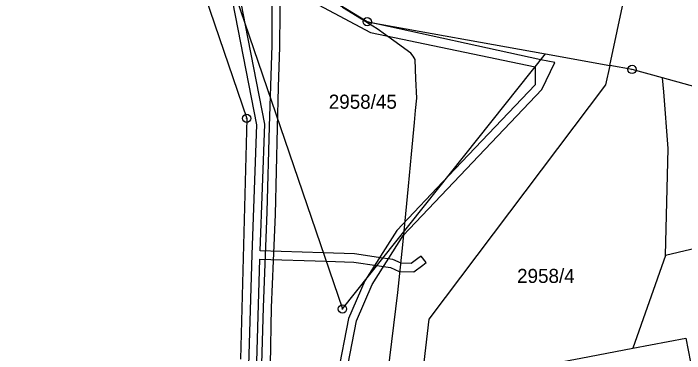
# Model space of a CAD drawing. Extents: x -621168 to -620292, y -1122748 to -1122069.
# Drawn here: x -620574.7 to -620493.7, y -1122640.4 to -1122599.3 of the extents above; entities that cross this region are included whole.
import ezdxf

# ---------------------------------------------------------------- set-up
doc = ezdxf.new("R2010")
doc.units = 0
for name, color, linetype in [('GasNet', 7, 'Continuous'), ('Hranice parcel', 7, 'Continuous'), ('Parcelní čísla', 7, 'Continuous'), ('VAS stoka', 7, 'Continuous'), ('VAS vodovod', 7, 'Continuous'), ('Vnitřní kresba', 7, 'Continuous'), ('Věcná břemena k části', 7, 'Continuous'), ('Značky bodu BP', 7, 'Continuous')]:
    doc.layers.add(name, color=color, linetype=linetype)

msp = doc.modelspace()

# ---------------------------------------------------------------- linework, layer by layer
at = {"layer": 'GasNet'}
msp.add_lwpolyline([(-620543.45, -1122595.16), (-620543.47, -1122603.15), (-620543.79, -1122613), (-620544.07, -1122623.3), (-620544.52, -1122634.84), (-620544.92, -1122648.49), (-620545.38, -1122658.87), (-620545.7, -1122668.76), (-620545.98, -1122679.66), (-620545.725, -1122687.651)], dxfattribs=at)
at = {"layer": 'Hranice parcel'}
for p, q in [((-620510.44, -1122604.21), (-620502.69, -1122605.61)), ((-620546.5, -1122612), (-620547.23, -1122641.1))]:
    msp.add_line(p, q, dxfattribs=at)
for points in [[(-620581.67, -1122552.32), (-620562.67, -1122564.59), (-620546.5, -1122612)], [(-620562.8, -1122553.35), (-620548.28, -1122570.88), (-620537.83, -1122596.73), (-620531.96, -1122600.32), (-620510.44, -1122604.21)], [(-620562.8, -1122553.35), (-620534.95, -1122635.03), (-620510.44, -1122604.21)], [(-620502.69, -1122605.61), (-620500.92, -1122597.26), (-620501.2, -1122595.75)], [(-620502.69, -1122605.61), (-620503.19, -1122607.95), (-620524.52, -1122636.25), (-620525.13, -1122641.47), (-620525.33, -1122649.53), (-620522.29, -1122666.99)], [(-620496.31, -1122607.11), (-620500, -1122606.09), (-620502.69, -1122605.61)], [(-620485.31, -1122626.04), (-620487.46, -1122626.56), (-620495.96, -1122628.58), (-620495.65, -1122615.65), (-620496.18, -1122608.79), (-620496.31, -1122607.11)], [(-620478.83, -1122611.96), (-620480.79, -1122611.41), (-620496.31, -1122607.11)], [(-620522.29, -1122666.99), (-620515.05, -1122665.61), (-620511.55, -1122664.94), (-620512.68, -1122659.03), (-620515.78, -1122642.8), (-620506.17, -1122640.97), (-620499.9, -1122639.77), (-620493.5, -1122638.55), (-620492.94, -1122641.47), (-620486.3, -1122676.15)]]:
    msp.add_lwpolyline(points, dxfattribs=at)
at = {"layer": 'VAS stoka'}
msp.add_lwpolyline([(-620529.696, -1122644.88), (-620528.987, -1122638.954), (-620528.278, -1122633.029), (-620527.953, -1122629.96), (-620527.627, -1122626.89), (-620527.309, -1122623.538), (-620526.991, -1122620.187), (-620526.62, -1122616.34), (-620526.248, -1122612.494), (-620526.118, -1122611.034), (-620525.987, -1122609.574), (-620526.074, -1122607.233), (-620526.16, -1122604.893), (-620526.431, -1122604.504), (-620526.702, -1122604.116), (-620528.728, -1122602.652), (-620530.754, -1122601.188), (-620532.839, -1122599.89), (-620534.923, -1122598.593)], dxfattribs=at)
at = {"layer": 'VAS vodovod'}
msp.add_lwpolyline([(-620544.967, -1122587.097), (-620544.948, -1122587.248), (-620544.929, -1122587.398), (-620544.87, -1122587.521), (-620544.812, -1122587.644), (-620544.235, -1122589.495), (-620543.658, -1122591.345), (-620543.047, -1122593.188), (-620542.435, -1122595.031), (-620542.492, -1122599.187), (-620542.549, -1122603.343), (-620542.689, -1122608.247), (-620542.829, -1122613.151), (-620542.948, -1122618.376), (-620543.067, -1122623.6), (-620543.31, -1122629.222), (-620543.553, -1122634.844), (-620543.681, -1122641.775)], dxfattribs=at)
at = {"layer": 'Vnitřní kresba'}
msp.add_line((-620495.96, -1122628.58), (-620499.9, -1122639.77), dxfattribs=at)
at = {"layer": 'Věcná břemena k části'}
for points in [[(-620534.53, -1122643.11), (-620533.24, -1122636.48), (-620531.35, -1122632.09), (-620527.61, -1122626.14), (-620510.87, -1122608.51), (-620509.33, -1122605.27), (-620511, -1122604.91), (-620531.96, -1122600.32), (-620537.83, -1122596.73), (-620543.57, -1122594.05), (-620549.38, -1122589.64), (-620555.33, -1122573.96), (-620556.49, -1122571.86), (-620550.21, -1122590.27), (-620544.11, -1122594.89), (-620531.56, -1122601.62), (-620511.69, -1122605.79), (-620511.71, -1122607.93), (-620522.17, -1122618.96), (-620528.4, -1122625.53), (-620532.24, -1122631.63), (-620534.2, -1122636.18), (-620535.53, -1122643.03)], [(-620545.91, -1122663.42), (-620544.9, -1122629), (-620536.91, -1122629.27), (-620533.56, -1122629.38), (-620530.78, -1122629.78), (-620529.16, -1122630.02), (-620528.1, -1122630.5), (-620526.34, -1122630.56), (-620525.24, -1122629.73), (-620524.84, -1122629.43), (-620525.44, -1122628.63), (-620525.84, -1122628.93), (-620526.66, -1122629.54), (-620527.88, -1122629.5), (-620528.88, -1122629.06), (-620530.06, -1122628.89), (-620533.48, -1122628.38), (-620537.26, -1122628.25), (-620544.86, -1122628), (-620544.3, -1122612.69), (-620546.64, -1122600.75), (-620547.87, -1122594.46)], [(-620548.87, -1122594.56), (-620545.3, -1122612.77), (-620545.88, -1122628.46), (-620546.91, -1122663.38)]]:
    msp.add_lwpolyline(points, dxfattribs=at)
at = {"layer": 'Značky bodu BP'}
for centre, radius in [((-620531.96, -1122600.32), 0.5), ((-620531.96, -1122600.32), 0.0303), ((-620500, -1122606.09), 0.5), ((-620500, -1122606.09), 0.0303), ((-620546.5, -1122612), 0.5), ((-620546.5, -1122612), 0.0303), ((-620534.95, -1122635.03), 0.5), ((-620534.95, -1122635.03), 0.0303)]:
    msp.add_circle(centre, radius, dxfattribs=at)

# ---------------------------------------------------------------- texts
at = {"layer": 'Parcelní čísla'}
for s, p in [('2958/45', (-620536.598, -1122610.836)), ('2958/4', (-620513.875, -1122631.886))]:
    msp.add_text(s, height=1.7, dxfattribs=at).set_placement(p)

doc.saveas('drawing.dxf')
